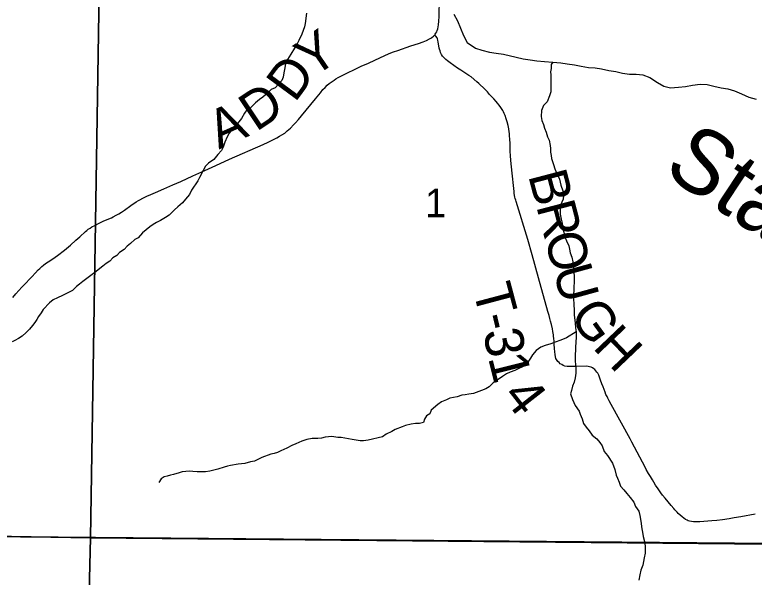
# Model space of a CAD drawing. Extents: x 0 to 34, y 0 to 22.
# Drawn here: x 23.114 to 24.203, y 14.542 to 15.371 of the extents above; entities that cross this region are included whole.
import ezdxf

# ---------------------------------------------------------------- set-up
doc = ezdxf.new("R2010")
doc.units = 0
for name, color, linetype in [('GM_X_Corporation', 7, 'Continuous'), ('GM_X_Major_River', 7, 'Continuous'), ('GM_X_Major_River_Text', 7, 'Continuous'), ('GM_X_Minor_River', 7, 'Continuous'), ('GM_X_Section_Text', 7, 'Continuous'), ('GM_X_Township_Road', 7, 'Continuous'), ('GM_X_Township_Road_Text', 7, 'Continuous')]:
    doc.layers.add(name, color=color, linetype=linetype)

msp = doc.modelspace()

# ---------------------------------------------------------------- linework, layer by layer
at = {"layer": 'GM_X_Corporation'}
msp.add_lwpolyline([(20.2208, 16.9558), (20.1987, 15.2691), (20.203, 14.81), (20.2016, 14.6512), (20.2571, 14.6508), (21.1282, 14.6279), (21.314, 14.623), (22.3464, 14.612), (22.9003, 14.6033), (24.2301, 14.5912), (24.2265, 14.4444), (24.4406, 14.442), (25.338, 14.4317), (25.4, 14.4307), (25.4, 19.0068)], dxfattribs=at)
for points in [[(22.2224, 15.6282), (23.2418, 15.623), (23.2254, 14.5998), (22.2045, 14.6168)], [(23.2418, 15.623), (24.2407, 15.6067), (24.2392, 15.4615), (24.2269, 14.5903), (23.2254, 14.5998)], [(18.6, 14.6606), (18.6, 13.6), (24.2109, 13.6), (24.2228, 14.2453), (24.2265, 14.4444), (24.2301, 14.5912), (22.9003, 14.6033), (22.3464, 14.612), (21.314, 14.623), (21.1282, 14.6279), (20.2571, 14.6508), (20.2016, 14.6512), (19.8855, 14.6528), (19.4007, 14.6554), (18.9216, 14.6592)], [(22.2045, 14.6168), (23.2254, 14.5998), (23.2038, 13.7171), (22.1889, 13.7096)], [(23.2254, 14.5998), (24.2269, 14.5903), (24.2243, 14.4432), (24.2104, 13.724), (23.2038, 13.7171)]]:
    msp.add_lwpolyline(points, close=True, dxfattribs=at)
at = {"layer": 'GM_X_Major_River'}
msp.add_lwpolyline([(23.7606, 15.3719), (23.7664, 15.3621), (23.7706, 15.3515), (23.7749, 15.3405), (23.7806, 15.3303), (23.7925, 15.322), (23.802, 15.3187), (23.8134, 15.3161), (23.8232, 15.3143), (23.8338, 15.3129), (23.8528, 15.3085), (23.8631, 15.3063), (23.8733, 15.3045), (23.8832, 15.303), (23.8946, 15.302), (23.9067, 15.3013), (23.9185, 15.3003), (23.9279, 15.2989), (23.9386, 15.2971), (23.9484, 15.2952), (23.9591, 15.2934), (23.9689, 15.2928), (23.9784, 15.2913), (23.9894, 15.2888), (23.9997, 15.2873), (24.0095, 15.2851), (24.0198, 15.2833), (24.0296, 15.2834), (24.0395, 15.2827), (24.0498, 15.2783), (24.0608, 15.2711), (24.0703, 15.2659), (24.0802, 15.2633), (24.092, 15.2642), (24.1022, 15.2654), (24.1124, 15.2674), (24.1238, 15.2686), (24.134, 15.2683), (24.1439, 15.2658), (24.1545, 15.2632), (24.1647, 15.2618), (24.1746, 15.2588), (24.1849, 15.2543), (24.1955, 15.2495), (24.2062, 15.2466)], dxfattribs=at)
at = {"layer": 'GM_X_Minor_River'}
for points in [[(23.5438, 15.3735), (23.5419, 15.3582), (23.5408, 15.3533), (23.537, 15.3423), (23.5325, 15.3331), (23.5295, 15.3274), (23.5261, 15.3217), (23.5204, 15.313), (23.5159, 15.3053), (23.5128, 15.2985), (23.5113, 15.2901), (23.5102, 15.2852), (23.5091, 15.2791), (23.5072, 15.2741), (23.4974, 15.2635), (23.4917, 15.2608), (23.4868, 15.2558), (23.4792, 15.2494), (23.4743, 15.2463), (23.4686, 15.2414), (23.4606, 15.2334), (23.4557, 15.2307), (23.4523, 15.2261), (23.4481, 15.2181), (23.4398, 15.2082), (23.4341, 15.2018), (23.4296, 15.1964), (23.4269, 15.1911), (23.4235, 15.1831), (23.4209, 15.1759), (23.4183, 15.1709), (23.413, 15.1652), (23.4069, 15.1576), (23.399, 15.1523), (23.3948, 15.1477), (23.3914, 15.1416), (23.3861, 15.1313), (23.3835, 15.126), (23.3744, 15.1123), (23.3714, 15.1058), (23.3653, 15.099), (23.3608, 15.0936), (23.3539, 15.0879), (23.349, 15.0833), (23.3411, 15.0753), (23.3358, 15.0723), (23.3286, 15.0677), (23.3225, 15.0647), (23.3179, 15.062), (23.3126, 15.0582), (23.3073, 15.054), (23.302, 15.0494), (23.2956, 15.0422), (23.2907, 15.0395), (23.2842, 15.0338), (23.2793, 15.0296), (23.2751, 15.025), (23.2683, 15.0205), (23.2642, 15.0159), (23.2585, 15.0125), (23.2536, 15.0079), (23.2486, 15.0045), (23.2437, 15.0003), (23.2392, 14.9968), (23.2339, 14.9923), (23.2142, 14.9779)], [(23.9067, 15.3013), (23.9043, 15.2977), (23.9043, 15.2916), (23.9032, 15.2871), (23.9036, 15.2825), (23.9036, 15.2574), (23.9017, 15.2517), (23.8983, 15.2429), (23.893, 15.2372), (23.89, 15.23), (23.8893, 15.2212), (23.8904, 15.2152), (23.8927, 15.2091), (23.8946, 15.2038), (23.8966, 15.1981), (23.8989, 15.1908), (23.9011, 15.1863), (23.9027, 15.1783), (23.9031, 15.1737), (23.9031, 15.1684), (23.9042, 15.1635), (23.9046, 15.1589), (23.9077, 15.1502), (23.9096, 15.1441), (23.9123, 15.138), (23.9165, 15.1285), (23.9184, 15.1198), (23.9215, 15.1114), (23.9226, 15.1046), (23.9219, 15.0993), (23.92, 15.0947), (23.9177, 15.0882), (23.9174, 15.0829), (23.9174, 15.0768), (23.9189, 15.0696), (23.9205, 15.0639), (23.9216, 15.0552), (23.9235, 15.0483), (23.9243, 15.0434), (23.927, 15.0377), (23.93, 15.0301), (23.9312, 15.0255), (23.9323, 15.0198), (23.9346, 15.0134), (23.9362, 15.0069), (23.9366, 15.0008), (23.9374, 14.9932), (23.9381, 14.9833), (23.9382, 14.9765), (23.9378, 14.97), (23.9374, 14.9647), (23.9371, 14.9586), (23.9371, 14.9525), (23.9375, 14.9438), (23.9379, 14.9354), (23.9383, 14.9286), (23.9395, 14.9164), (23.9402, 14.9096), (23.941, 14.9035), (23.941, 14.8959), (23.9407, 14.8879), (23.9403, 14.8815), (23.94, 14.8769), (23.9396, 14.8697), (23.9396, 14.8602), (23.94, 14.8552), (23.9404, 14.8492), (23.9408, 14.8423), (23.9397, 14.8358), (23.9382, 14.8294), (23.9356, 14.8233), (23.9344, 14.8172), (23.9329, 14.8119), (23.9356, 14.8039), (23.9375, 14.7994), (23.9398, 14.7948), (23.9455, 14.7864), (23.9471, 14.7819), (23.9501, 14.7751), (23.952, 14.7682), (23.9559, 14.7629), (23.9604, 14.7576), (23.9646, 14.7511), (23.9715, 14.7455), (23.9757, 14.7405), (23.9795, 14.7352), (23.9822, 14.7272), (23.9871, 14.7212), (23.9947, 14.7098), (23.9982, 14.7003), (24.0001, 14.6923), (24.002, 14.6877), (24.0043, 14.682), (24.0066, 14.676), (24.0112, 14.6703), (24.0158, 14.6653), (24.0207, 14.6593), (24.026, 14.6524), (24.0287, 14.646), (24.0333, 14.6392), (24.0348, 14.6327)], [(23.2142, 14.9779), (23.2141, 14.9778), (23.2092, 14.9739), (23.2047, 14.9701), (23.1987, 14.9646), (23.1912, 14.9603), (23.1841, 14.9572), (23.1769, 14.9536), (23.1701, 14.9505), (23.1649, 14.9462), (23.1556, 14.9365), (23.1526, 14.9315), (23.1489, 14.9261), (23.1463, 14.9219), (23.1433, 14.9173), (23.14, 14.9127), (23.1355, 14.9073), (23.1307, 14.9026), (23.1247, 14.8972), (23.1191, 14.8937), (23.1138, 14.8906), (23.1097, 14.8886)], [(23.941, 14.9034), (23.927, 14.8947), (23.9183, 14.8913), (23.9099, 14.8882), (23.9035, 14.886), (23.8955, 14.8833), (23.8891, 14.881), (23.8823, 14.876), (23.8766, 14.8696), (23.8739, 14.8646), (23.8698, 14.8589), (23.8667, 14.8543), (23.8622, 14.8517), (23.8558, 14.849), (23.8508, 14.8463), (23.844, 14.844), (23.8383, 14.8414), (23.8326, 14.8375), (23.8232, 14.8314), (23.8186, 14.8284), (23.8126, 14.8223), (23.808, 14.8192), (23.8016, 14.817), (23.7898, 14.8124), (23.783, 14.8116), (23.7777, 14.8108), (23.7727, 14.8101), (23.7655, 14.8078), (23.7549, 14.8055), (23.75, 14.8032), (23.7424, 14.8005), (23.7371, 14.7963), (23.7276, 14.7879), (23.7253, 14.7826), (23.7204, 14.7796), (23.7174, 14.7746), (23.7163, 14.77), (23.7102, 14.7685), (23.7041, 14.7681), (23.6981, 14.7673), (23.6897, 14.7654), (23.6848, 14.7635), (23.6745, 14.7593), (23.6696, 14.7566), (23.6613, 14.7525), (23.6556, 14.7486), (23.6343, 14.7437), (23.6279, 14.7429), (23.6226, 14.7429), (23.6108, 14.7448), (23.6055, 14.7459), (23.5948, 14.7478), (23.5899, 14.7478), (23.5808, 14.7493), (23.5759, 14.7485), (23.5713, 14.7481), (23.5656, 14.7466), (23.5603, 14.7462), (23.5519, 14.7462), (23.544, 14.7446), (23.5368, 14.7423), (23.5277, 14.7385), (23.522, 14.7358), (23.5148, 14.732), (23.5057, 14.7278), (23.5011, 14.7255), (23.4958, 14.724), (23.4913, 14.7229), (23.478, 14.7183), (23.467, 14.7129), (23.4613, 14.7118), (23.453, 14.7095), (23.4431, 14.7083), (23.4317, 14.7064), (23.4272, 14.7053), (23.4222, 14.7041), (23.4131, 14.701), (23.401, 14.698), (23.3949, 14.6972), (23.3904, 14.6968), (23.3824, 14.6968), (23.3763, 14.6976), (23.371, 14.6979), (23.3657, 14.6975), (23.3604, 14.6968), (23.3558, 14.6956), (23.3478, 14.6933), (23.3433, 14.6922), (23.3384, 14.6906), (23.3338, 14.6895), (23.3293, 14.6868), (23.3262, 14.6815)], [(24.0348, 14.6327), (24.0364, 14.6243), (24.0376, 14.6129), (24.0387, 14.608), (24.0399, 14.6015), (24.0422, 14.5924), (24.0426, 14.586), (24.0426, 14.5769), (24.0415, 14.5704), (24.0392, 14.5594), (24.0362, 14.5518), (24.0347, 14.5453), (24.0332, 14.5373)]]:
    msp.add_lwpolyline(points, dxfattribs=at)
at = {"layer": 'GM_X_Township_Road'}
for points in [[(23.3762, 15.1334), (23.3938, 15.1416), (23.4102, 15.149), (23.4303, 15.158), (23.4798, 15.1798), (23.4873, 15.1833), (23.4942, 15.1866), (23.5001, 15.1896), (23.504, 15.1918), (23.5075, 15.1938), (23.5115, 15.1966), (23.5153, 15.1998), (23.5202, 15.204), (23.5246, 15.2086), (23.5276, 15.2116), (23.5318, 15.2164), (23.5365, 15.222), (23.557, 15.2471), (23.5641, 15.2561), (23.5679, 15.2608), (23.571, 15.264), (23.5743, 15.2672), (23.5772, 15.2695), (23.5844, 15.2747), (23.587, 15.2765), (23.5905, 15.2787), (23.5943, 15.2807), (23.6244, 15.2952), (23.6349, 15.2998), (23.6525, 15.3082), (23.658, 15.3107), (23.6655, 15.3138), (23.6721, 15.3163), (23.6782, 15.3184), (23.6975, 15.325), (23.7087, 15.3288), (23.7155, 15.3313), (23.7207, 15.3333), (23.7249, 15.3355), (23.727, 15.3367), (23.7285, 15.3377), (23.7306, 15.3395), (23.7327, 15.3417), (23.7333, 15.3425), (23.7344, 15.3439), (23.7355, 15.3457), (23.7364, 15.3477), (23.7372, 15.3502), (23.7378, 15.3531), (23.7384, 15.3564), (23.7388, 15.3618), (23.739, 15.3684), (23.7406, 15.4488)], [(24.2047, 14.6348), (24.1836, 14.6309), (24.1738, 14.6291), (24.1663, 14.6279), (24.1565, 14.6264), (24.1483, 14.6255), (24.1411, 14.6247), (24.1353, 14.6242), (24.1294, 14.6238), (24.1232, 14.6233), (24.1186, 14.6233), (24.1142, 14.6234), (24.1109, 14.6238), (24.1083, 14.6244), (24.1063, 14.625), (24.1044, 14.6258), (24.1024, 14.6268), (24.0999, 14.6285), (24.0972, 14.6306), (24.0944, 14.6329), (24.0916, 14.6355), (24.0897, 14.6376), (24.0878, 14.6395), (24.0864, 14.6412), (24.0848, 14.6429), (24.0811, 14.6473), (24.0764, 14.6527), (24.072, 14.6581), (24.0684, 14.6626), (24.066, 14.6659), (24.0639, 14.6689), (24.0617, 14.6721), (24.0582, 14.6776), (24.0555, 14.6817), (24.0533, 14.6854), (24.0505, 14.6902), (24.0478, 14.6946), (24.0444, 14.7006), (24.0416, 14.7057), (24.0386, 14.7113), (24.0231, 14.7407), (24.0204, 14.7458), (23.9925, 14.7964), (23.9897, 14.8019), (23.9878, 14.8055), (23.9865, 14.808), (23.9848, 14.8113), (23.9836, 14.8143), (23.9821, 14.8186), (23.9808, 14.8222), (23.9791, 14.8267), (23.9771, 14.8323), (23.9755, 14.8368), (23.9743, 14.8395), (23.9728, 14.8424), (23.9716, 14.8442), (23.9702, 14.8461), (23.9685, 14.8478), (23.9671, 14.849), (23.965, 14.8504), (23.963, 14.8513), (23.9609, 14.852), (23.9589, 14.8525), (23.9569, 14.8527), (23.9401, 14.8525), (23.9277, 14.8526), (23.9244, 14.853), (23.9221, 14.8539), (23.9197, 14.8551), (23.9177, 14.8565), (23.9158, 14.8582), (23.9142, 14.8598), (23.9129, 14.8614), (23.9119, 14.8629), (23.9112, 14.8643), (23.9104, 14.8667), (23.9099, 14.8701), (23.9095, 14.8741), (23.9092, 14.8791), (23.9088, 14.8851), (23.9085, 14.8898), (23.9082, 14.8936), (23.9078, 14.8971), (23.9075, 14.8992), (23.9066, 14.9041), (23.906, 14.9077), (23.9046, 14.9143), (23.9034, 14.9192), (23.9024, 14.9233), (23.9012, 14.9278), (23.8995, 14.9336), (23.8855, 14.9832), (23.8762, 15.0172), (23.87, 15.0395), (23.8527, 15.0956), (23.852, 15.0978), (23.8513, 15.1001), (23.8508, 15.1023), (23.8503, 15.1047), (23.8498, 15.108), (23.8495, 15.1104), (23.8462, 15.142), (23.8457, 15.1475), (23.8454, 15.1506), (23.8448, 15.1571), (23.8444, 15.1627), (23.844, 15.1705), (23.8436, 15.1812), (23.8433, 15.1878), (23.843, 15.1926), (23.8427, 15.1958), (23.8423, 15.1986), (23.8416, 15.2029), (23.8406, 15.2079), (23.8393, 15.2133), (23.8381, 15.2174), (23.8362, 15.2224), (23.8351, 15.2254), (23.8338, 15.2279), (23.8328, 15.2298), (23.8299, 15.2342), (23.8275, 15.2376), (23.825, 15.2408), (23.823, 15.2431), (23.8196, 15.2469), (23.8135, 15.2537), (23.8103, 15.2572), (23.8064, 15.2612), (23.7976, 15.2698), (23.7947, 15.2723), (23.7861, 15.2793), (23.783, 15.2815), (23.7712, 15.2892), (23.7664, 15.2923), (23.7553, 15.3002), (23.7515, 15.3029), (23.7489, 15.3052), (23.7466, 15.3074), (23.7443, 15.3101), (23.7426, 15.3125), (23.7413, 15.3154), (23.7404, 15.318), (23.7397, 15.3202), (23.7393, 15.3219), (23.7377, 15.3312), (23.7373, 15.3332), (23.7365, 15.3361), (23.7361, 15.3371), (23.7344, 15.3397), (23.7327, 15.3417)], [(23.1107, 14.9539), (23.1154, 14.9594), (23.1198, 14.9642), (23.1243, 14.9693), (23.1304, 14.9757), (23.1351, 14.9806), (23.1391, 14.9848), (23.1443, 14.9903), (23.1483, 14.9947), (23.1508, 14.9971), (23.1535, 14.9997), (23.1562, 15.0018), (23.1591, 15.0041), (23.1669, 15.0092), (23.1731, 15.0134), (23.1767, 15.0161), (23.1868, 15.024), (23.1957, 15.0315), (23.2039, 15.0386), (23.2096, 15.0436), (23.2179, 15.0515), (23.2199, 15.0531), (23.222, 15.0547), (23.2248, 15.0566), (23.2274, 15.0582), (23.2319, 15.0605), (23.2379, 15.0635), (23.2452, 15.067), (23.2561, 15.0718), (23.2588, 15.0732), (23.2632, 15.0755), (23.2671, 15.0777), (23.2708, 15.0798), (23.2753, 15.0828), (23.2849, 15.0898), (23.2927, 15.0951), (23.2959, 15.097), (23.3045, 15.1015), (23.3082, 15.1034), (23.3144, 15.1061), (23.3211, 15.1091), (23.3335, 15.1143), (23.3468, 15.1202), (23.3587, 15.1254), (23.3762, 15.1334)]]:
    msp.add_lwpolyline(points, dxfattribs=at)

# ---------------------------------------------------------------- texts
at = {"layer": 'GM_X_Major_River_Text'}
msp.add_text('Standingstone', height=0.094695, rotation=326.5804, dxfattribs=at).set_placement((24.0668, 15.138))
at = {"layer": 'GM_X_Section_Text'}
msp.add_text('1', height=0.0419, rotation=0, dxfattribs=at).set_placement((23.7183, 15.0725))
at = {"layer": 'GM_X_Township_Road_Text'}
for s, rotation, p in [('Y', 34.3498, (23.5525, 15.277)), ('D', 53.5908, (23.5264, 15.2402)), ('D', 33.7121, (23.4693, 15.1977)), ('A', 24.0816, (23.4145, 15.1722)), ('B', 284.6951, (23.87, 15.1344)), ('R', 284.6951, (23.8819, 15.0893)), ('O', 284.6954, (23.8937, 15.0442)), ('U', 285.3899, (23.9066, 14.9951)), ('T', 284.8928, (23.7881, 14.9669)), ('G', 305.8662, (23.9294, 14.927)), ('-', 283.4247, (23.7989, 14.9262)), ('3', 279.8371, (23.8041, 14.9044)), ('H', 313.6559, (23.9641, 14.88)), ('1', 283.9009, (23.811, 14.8656)), ('4', 308.0307, (23.8307, 14.8084))]:
    msp.add_text(s, height=0.0568, rotation=rotation, dxfattribs=at).set_placement(p)

doc.saveas('drawing.dxf')
